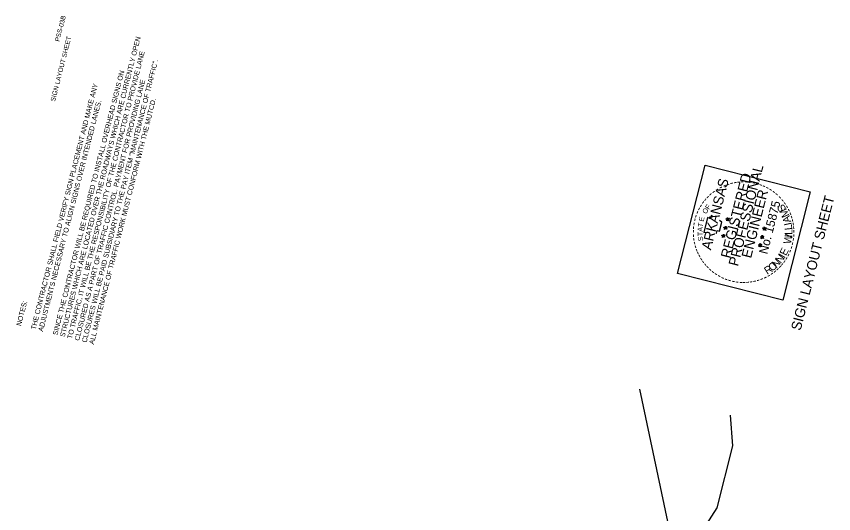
# Model space of a CAD drawing. Extents: x 670003 to 670131, y 737835 to 738003.
# Drawn here: x 670028.6 to 670130.8, y 737940.4 to 738002.6 of the extents above; entities that cross this region are included whole.
import ezdxf

# ---------------------------------------------------------------- set-up
doc = ezdxf.new("R2010")
doc.units = 0
for name, color, linetype in [('R_Alt Surface', 7, 'Continuous'), ('R_Border', 7, 'Continuous'), ('R_Border Notes', 7, 'Continuous'), ('R_Border PE', 7, 'Continuous'), ('R_Border Prem', 7, 'Continuous'), ('R_Exist Surface', 7, 'Continuous'), ('R_SIGN_ANNOT', 7, 'Continuous')]:
    doc.layers.add(name, color=color, linetype=linetype)

msp = doc.modelspace()

# ---------------------------------------------------------------- linework, layer by layer
at = {"layer": 'R_Alt Surface'}
for points in [[(670116.21, 737941.14), (670118.18, 737948.89), (670117.89, 737952.73)], [(670102.43, 737911.4), (670104, 737916.67), (670111.54, 737933.85), (670116.21, 737941.14)]]:
    msp.add_lwpolyline(points, dxfattribs=at)
at = {"layer": 'R_Border PE'}
for p, q in [((670117.32, 737977.26), (670117.48, 737977.27)), ((670117.53, 737977.21), (670117.32, 737977.26)), ((670117.32, 737977.26), (670117.47, 737977.25)), ((670117.32, 737977.26), (670117.46, 737977.24)), ((670117.32, 737977.26), (670117.46, 737977.21)), ((670117.32, 737977.26), (670117.46, 737977.2)), ((670117.32, 737977.26), (670117.45, 737977.19)), ((670117.41, 737977.01), (670117.53, 737977.21)), ((670117.41, 737977.01), (670117.47, 737977.16)), ((670117.41, 737977.01), (670117.48, 737977.15)), ((670117.41, 737977.01), (670117.49, 737977.15)), ((670117.41, 737977.01), (670117.51, 737977.14)), ((670117.41, 737977.01), (670117.52, 737977.14)), ((670117.41, 737977.01), (670117.53, 737977.13)), ((670117.52, 737977.44), (670117.49, 737977.24)), ((670117.52, 737977.44), (670117.51, 737977.25)), ((670117.52, 737977.44), (670117.53, 737977.21)), ((670117.52, 737977.44), (670117.52, 737977.25)), ((670117.52, 737977.44), (670117.54, 737977.29)), ((670117.52, 737977.44), (670117.55, 737977.29)), ((670117.52, 737977.44), (670117.56, 737977.3)), ((670117.75, 737977.29), (670117.53, 737977.21)), ((670117.68, 737977.03), (670117.53, 737977.21)), ((670117.68, 737977.03), (670117.53, 737977.14)), ((670117.75, 737977.29), (670117.55, 737977.25)), ((670117.68, 737977.03), (670117.55, 737977.14)), ((670117.75, 737977.29), (670117.56, 737977.27)), ((670117.68, 737977.03), (670117.56, 737977.15)), ((670117.75, 737977.29), (670117.57, 737977.24)), ((670117.75, 737977.29), (670117.58, 737977.19)), ((670117.68, 737977.03), (670117.58, 737977.19)), ((670117.68, 737977.03), (670117.58, 737977.17)), ((670117.75, 737977.29), (670117.59, 737977.22)), ((670117.75, 737977.29), (670117.6, 737977.19)), ((670117.68, 737977.03), (670117.6, 737977.2)), ((670117.26, 737976.14), (670117.03, 737976.19)), ((670117.03, 737976.19), (670117.2, 737976.19)), ((670117.03, 737976.19), (670117.19, 737976.18)), ((670117.03, 737976.19), (670117.19, 737976.17)), ((670117.03, 737976.19), (670117.18, 737976.14)), ((670117.03, 737976.19), (670117.18, 737976.13)), ((670117.03, 737976.19), (670117.18, 737976.12)), ((670117.14, 737975.94), (670117.26, 737976.14)), ((670117.14, 737975.94), (670117.19, 737976.09)), ((670117.14, 737975.94), (670117.2, 737976.09)), ((670117.14, 737975.94), (670117.21, 737976.08)), ((670117.14, 737975.94), (670117.23, 737976.07)), ((670117.14, 737975.94), (670117.24, 737976.07)), ((670117.14, 737975.94), (670117.26, 737976.06)), ((670117.24, 737976.36), (670117.21, 737976.17)), ((670117.24, 737976.36), (670117.23, 737976.18)), ((670117.24, 737976.36), (670117.26, 737976.14)), ((670117.24, 737976.36), (670117.24, 737976.18)), ((670117.24, 737976.36), (670117.26, 737976.22)), ((670117.24, 737976.36), (670117.27, 737976.23)), ((670117.24, 737976.36), (670117.28, 737976.23)), ((670117.41, 737975.96), (670117.25, 737976.07)), ((670117.47, 737976.22), (670117.26, 737976.14)), ((670117.41, 737975.96), (670117.26, 737976.14)), ((670117.47, 737976.22), (670117.27, 737976.18)), ((670117.47, 737976.22), (670117.27, 737976.2)), ((670117.41, 737975.96), (670117.27, 737976.07)), ((670117.41, 737975.96), (670117.28, 737976.08)), ((670117.47, 737976.22), (670117.3, 737976.12)), ((670117.47, 737976.22), (670117.3, 737976.17)), ((670117.41, 737975.96), (670117.3, 737976.12)), ((670117.41, 737975.96), (670117.3, 737976.1)), ((670117.47, 737976.22), (670117.32, 737976.12)), ((670117.47, 737976.22), (670117.32, 737976.15)), ((670117.41, 737975.96), (670117.32, 737976.12)), ((670122.12, 737976.04), (670121.9, 737976.1)), ((670121.9, 737976.1), (670122.06, 737976.1)), ((670121.9, 737976.1), (670122.06, 737976.09)), ((670121.9, 737976.1), (670122.06, 737976.07)), ((670121.9, 737976.1), (670122.05, 737976.05)), ((670121.9, 737976.1), (670122.05, 737976.04)), ((670121.9, 737976.1), (670122.04, 737976.02)), ((670122, 737975.85), (670122.12, 737976.04)), ((670122, 737975.85), (670122.06, 737975.99)), ((670122, 737975.85), (670122.07, 737975.99)), ((670122, 737975.85), (670122.08, 737975.98)), ((670122, 737975.85), (670122.1, 737975.98)), ((670122, 737975.85), (670122.11, 737975.97)), ((670122, 737975.85), (670122.13, 737975.96)), ((670122.11, 737976.27), (670122.07, 737976.08)), ((670122.11, 737976.27), (670122.09, 737976.09)), ((670122.11, 737976.27), (670122.1, 737976.09)), ((670122.11, 737976.27), (670122.12, 737976.04)), ((670122.11, 737976.27), (670122.13, 737976.12)), ((670122.11, 737976.27), (670122.14, 737976.13)), ((670122.11, 737976.27), (670122.15, 737976.13)), ((670122.27, 737975.86), (670122.11, 737975.97)), ((670122.33, 737976.12), (670122.12, 737976.04)), ((670122.27, 737975.86), (670122.12, 737976.04)), ((670122.33, 737976.12), (670122.14, 737976.08)), ((670122.33, 737976.12), (670122.14, 737976.1)), ((670122.27, 737975.86), (670122.14, 737975.97)), ((670122.27, 737975.86), (670122.15, 737975.99)), ((670122.33, 737976.12), (670122.17, 737976.02)), ((670122.33, 737976.12), (670122.17, 737976.07)), ((670122.27, 737975.86), (670122.17, 737976.02)), ((670122.27, 737975.86), (670122.17, 737976.01)), ((670122.33, 737976.12), (670122.18, 737976.05)), ((670122.33, 737976.12), (670122.19, 737976.02)), ((670122.27, 737975.86), (670122.19, 737976.03)), ((670117, 737975.12), (670116.77, 737975.18)), ((670116.77, 737975.18), (670116.94, 737975.18)), ((670116.77, 737975.18), (670116.93, 737975.17)), ((670116.77, 737975.18), (670116.93, 737975.16)), ((670116.77, 737975.18), (670116.92, 737975.14)), ((670116.77, 737975.18), (670116.93, 737975.12)), ((670116.77, 737975.18), (670116.92, 737975.11)), ((670116.88, 737974.93), (670117, 737975.12)), ((670116.88, 737974.93), (670116.93, 737975.08)), ((670116.88, 737974.93), (670116.94, 737975.08)), ((670116.88, 737974.93), (670116.95, 737975.07)), ((670116.88, 737974.93), (670116.98, 737975.06)), ((670116.88, 737974.93), (670116.99, 737975.06)), ((670116.88, 737974.93), (670117, 737975.05)), ((670116.99, 737975.35), (670116.95, 737975.16)), ((670116.99, 737975.35), (670116.97, 737975.17)), ((670116.99, 737975.35), (670116.98, 737975.17)), ((670116.99, 737975.35), (670117, 737975.12)), ((670116.99, 737975.35), (670117.01, 737975.21)), ((670116.99, 737975.35), (670117.02, 737975.22)), ((670116.99, 737975.35), (670117.02, 737975.22)), ((670117.21, 737975.21), (670117, 737975.12)), ((670117.15, 737974.95), (670117, 737975.12)), ((670117.15, 737974.95), (670117, 737975.06)), ((670117.21, 737975.21), (670117.01, 737975.18)), ((670117.21, 737975.21), (670117.02, 737975.17)), ((670117.15, 737974.95), (670117.02, 737975.07)), ((670117.15, 737974.95), (670117.02, 737975.06)), ((670117.21, 737975.21), (670117.04, 737975.16)), ((670117.21, 737975.21), (670117.05, 737975.11)), ((670117.15, 737974.95), (670117.05, 737975.11)), ((670117.15, 737974.95), (670117.05, 737975.09)), ((670117.21, 737975.21), (670117.06, 737975.13)), ((670117.21, 737975.21), (670117.07, 737975.11)), ((670117.15, 737974.95), (670117.07, 737975.11)), ((670121.84, 737974.97), (670121.62, 737975.03)), ((670121.62, 737975.03), (670121.78, 737975.03)), ((670121.62, 737975.03), (670121.78, 737975.02)), ((670121.62, 737975.03), (670121.78, 737975)), ((670121.62, 737975.03), (670121.77, 737974.98)), ((670121.62, 737975.03), (670121.77, 737974.97)), ((670121.62, 737975.03), (670121.76, 737974.95)), ((670121.72, 737974.78), (670121.84, 737974.97)), ((670121.72, 737974.78), (670121.78, 737974.92)), ((670121.72, 737974.78), (670121.79, 737974.92)), ((670121.72, 737974.78), (670121.8, 737974.92)), ((670121.72, 737974.78), (670121.82, 737974.91)), ((670121.72, 737974.78), (670121.83, 737974.9)), ((670121.72, 737974.78), (670121.84, 737974.9)), ((670121.83, 737975.2), (670121.79, 737975.01)), ((670121.83, 737975.2), (670121.81, 737975.02)), ((670121.83, 737975.2), (670121.84, 737974.97)), ((670121.83, 737975.2), (670121.83, 737975.01)), ((670121.83, 737975.2), (670121.85, 737975.05)), ((670121.83, 737975.2), (670121.86, 737975.06)), ((670121.83, 737975.2), (670121.87, 737975.07)), ((670122.06, 737975.05), (670121.84, 737974.97)), ((670121.99, 737974.79), (670121.84, 737974.97)), ((670121.99, 737974.79), (670121.84, 737974.91)), ((670122.06, 737975.05), (670121.86, 737975.01)), ((670122.06, 737975.05), (670121.86, 737975.03)), ((670121.99, 737974.79), (670121.86, 737974.91)), ((670121.99, 737974.79), (670121.87, 737974.92)), ((670122.06, 737975.05), (670121.88, 737975.01)), ((670121.99, 737974.79), (670121.89, 737974.96)), ((670121.99, 737974.79), (670121.89, 737974.93)), ((670122.06, 737975.05), (670121.9, 737974.96)), ((670122.06, 737975.05), (670121.9, 737974.98)), ((670122.06, 737975.05), (670121.91, 737974.95)), ((670121.99, 737974.79), (670121.91, 737974.96)), ((670121.59, 737973.96), (670121.37, 737974.02)), ((670121.37, 737974.02), (670121.53, 737974.02)), ((670121.37, 737974.02), (670121.53, 737974.01)), ((670121.37, 737974.02), (670121.52, 737973.99)), ((670121.37, 737974.02), (670121.52, 737973.97)), ((670121.37, 737974.02), (670121.51, 737973.95)), ((670121.37, 737974.02), (670121.5, 737973.94)), ((670121.46, 737973.77), (670121.59, 737973.96)), ((670121.46, 737973.77), (670121.52, 737973.92)), ((670121.46, 737973.77), (670121.53, 737973.91)), ((670121.46, 737973.77), (670121.54, 737973.91)), ((670121.46, 737973.77), (670121.56, 737973.9)), ((670121.46, 737973.77), (670121.57, 737973.89)), ((670121.46, 737973.77), (670121.59, 737973.89)), ((670121.57, 737974.19), (670121.54, 737974)), ((670121.57, 737974.19), (670121.56, 737974.01)), ((670121.57, 737974.19), (670121.59, 737973.96)), ((670121.57, 737974.19), (670121.57, 737974)), ((670121.57, 737974.19), (670121.59, 737974.04)), ((670121.57, 737974.19), (670121.6, 737974.05)), ((670121.57, 737974.19), (670121.62, 737974.06)), ((670121.73, 737973.78), (670121.58, 737973.9)), ((670121.8, 737974.04), (670121.59, 737973.96)), ((670121.73, 737973.78), (670121.59, 737973.96)), ((670121.8, 737974.04), (670121.6, 737974)), ((670121.8, 737974.04), (670121.61, 737974.02)), ((670121.73, 737973.78), (670121.61, 737973.9)), ((670121.73, 737973.78), (670121.62, 737973.91)), ((670121.8, 737974.04), (670121.63, 737974)), ((670121.73, 737973.78), (670121.63, 737973.95)), ((670121.73, 737973.78), (670121.63, 737973.92)), ((670121.8, 737974.04), (670121.64, 737973.95)), ((670121.8, 737974.04), (670121.64, 737973.96)), ((670121.8, 737974.04), (670121.65, 737973.94)), ((670121.73, 737973.78), (670121.65, 737973.94))]:
    msp.add_line(p, q, dxfattribs=at)
for points in [[(670115.63, 737977.54), (670115.48, 737977.67), (670115.39, 737977.25), (670115.01, 737977.44), (670114.54, 737975.56)], [(670116.08, 737975.48), (670116.13, 737975.47), (670116.23, 737975.8), (670116.51, 737975.7), (670116.79, 737976.83), (670116.5, 737977.04)], [(670117.32, 737977.26), (670117.75, 737977.29), (670117.41, 737977.01), (670117.52, 737977.44), (670117.68, 737977.03), (670117.32, 737977.26)], [(670114.54, 737975.56), (670115.08, 737975.59)], [(670117.03, 737976.19), (670117.47, 737976.22), (670117.14, 737975.94), (670117.24, 737976.36), (670117.41, 737975.96), (670117.03, 737976.19)], [(670121.9, 737976.1), (670122.33, 737976.12), (670122, 737975.85), (670122.11, 737976.27), (670122.27, 737975.86), (670121.9, 737976.1)], [(670116.77, 737975.18), (670117.21, 737975.21), (670116.88, 737974.93), (670116.99, 737975.35), (670117.15, 737974.95), (670116.77, 737975.18)], [(670121.62, 737975.03), (670122.06, 737975.05), (670121.72, 737974.78), (670121.83, 737975.2), (670121.99, 737974.79), (670121.62, 737975.03)], [(670121.37, 737974.02), (670121.8, 737974.04), (670121.46, 737973.77), (670121.57, 737974.19), (670121.73, 737973.78), (670121.37, 737974.02)]]:
    msp.add_lwpolyline(points, dxfattribs=at)
for centre, radius in [((670117.54, 737977.21), 0.108), ((670117.54, 737977.21), 0.0975), ((670117.54, 737977.21), 0.0904), ((670117.54, 737977.21), 0.083), ((670117.54, 737977.21), 0.0723), ((670117.54, 737977.21), 0.0619), ((670117.54, 737977.21), 0.0672), ((670117.54, 737977.21), 0.0533), ((670117.54, 737977.21), 0.0467), ((670117.54, 737977.21), 0.0388), ((670117.54, 737977.21), 0.031), ((670117.54, 737977.21), 0.0231), ((670117.54, 737977.21), 0.0185), ((670117.54, 737977.21), 0.00901), ((670117.26, 737976.14), 0.108), ((670117.26, 737976.14), 0.0975), ((670117.26, 737976.14), 0.0904), ((670117.26, 737976.14), 0.083), ((670117.26, 737976.14), 0.0723), ((670117.26, 737976.14), 0.0619), ((670117.26, 737976.14), 0.0672), ((670117.26, 737976.14), 0.0533), ((670117.26, 737976.14), 0.0467), ((670117.26, 737976.14), 0.0388), ((670117.26, 737976.14), 0.031), ((670117.26, 737976.14), 0.0231), ((670117.26, 737976.14), 0.0185), ((670117.26, 737976.14), 0.00901), ((670122.12, 737976.04), 0.108), ((670122.12, 737976.04), 0.0975), ((670122.12, 737976.04), 0.0904), ((670122.12, 737976.04), 0.083), ((670122.12, 737976.04), 0.0723), ((670122.12, 737976.04), 0.0672), ((670122.12, 737976.04), 0.0619), ((670122.12, 737976.04), 0.0533), ((670122.12, 737976.04), 0.0467), ((670122.12, 737976.04), 0.0388), ((670122.12, 737976.04), 0.031), ((670122.12, 737976.04), 0.0231), ((670122.12, 737976.04), 0.0185), ((670122.12, 737976.04), 0.00901), ((670117, 737975.13), 0.108), ((670117, 737975.13), 0.0975), ((670117, 737975.13), 0.0904), ((670117, 737975.13), 0.083), ((670117, 737975.13), 0.0723), ((670117, 737975.13), 0.0672), ((670117, 737975.13), 0.0619), ((670117, 737975.13), 0.0533), ((670117, 737975.13), 0.0467), ((670117, 737975.13), 0.0388), ((670117, 737975.13), 0.031), ((670117, 737975.13), 0.0231), ((670117, 737975.13), 0.0185), ((670117, 737975.13), 0.00901), ((670121.84, 737974.97), 0.108), ((670121.84, 737974.97), 0.0975), ((670121.84, 737974.97), 0.0904), ((670121.84, 737974.97), 0.083), ((670121.84, 737974.97), 0.0723), ((670121.84, 737974.97), 0.0672), ((670121.84, 737974.97), 0.0619), ((670121.84, 737974.97), 0.0533), ((670121.84, 737974.97), 0.0467), ((670121.84, 737974.97), 0.0388), ((670121.84, 737974.97), 0.031), ((670121.84, 737974.97), 0.0231), ((670121.84, 737974.97), 0.0185), ((670121.84, 737974.97), 0.00901), ((670121.59, 737973.96), 0.108), ((670121.59, 737973.96), 0.0975), ((670121.59, 737973.96), 0.0904), ((670121.59, 737973.96), 0.083), ((670121.59, 737973.96), 0.0723), ((670121.59, 737973.96), 0.0672), ((670121.59, 737973.96), 0.0619), ((670121.59, 737973.96), 0.0533), ((670121.59, 737973.96), 0.0467), ((670121.59, 737973.96), 0.0388), ((670121.59, 737973.96), 0.031), ((670121.59, 737973.96), 0.0231), ((670121.59, 737973.96), 0.0185), ((670121.59, 737973.96), 0.00901)]:
    msp.add_circle(centre, radius, dxfattribs=at)
at = {"layer": 'R_Border Prem'}
msp.add_lwpolyline([(670111.27, 737970.43), (670114.7, 737983.95), (670127.85, 737980.62), (670124.42, 737967.1)], close=True, dxfattribs=at)
at = {"layer": 'R_Exist Surface'}
msp.add_lwpolyline([(670106.5, 737955.96), (670111.38, 737932.93), (670111.49, 737932.44), (670111.5, 737932.42), (670111.75, 737931.4), (670112, 737930.45), (670111.98, 737930.4), (670111.02, 737926.65), (670110.93, 737926.54), (670109.57, 737925), (670103.15, 737910.71), (670100.52, 737904.76), (670095.74, 737887.59), (670089.99, 737866.93), (670089.12, 737859.5), (670089.03, 737858.69), (670088.89, 737857.11), (670088.05, 737846.44), (670087.72, 737842.3), (670087.68, 737841.87), (670087.51, 737841.51), (670087.26, 737840.96)], dxfattribs=at)

# ---------------------------------------------------------------- texts
at = {"layer": 'R_Border'}
for s, height, p in [('PSS-03B', 0.586, (670034.01, 737999.36)), ('SIGN LAYOUT SHEET', 0.5862, (670033.46, 737991.88))]:
    msp.add_text(s, height=height, rotation=75.7686, dxfattribs=at).set_placement(p)
at = {"layer": 'R_Border Notes'}
msp.add_text('SIGN LAYOUT SHEET', height=1.25, rotation=75.7686, dxfattribs=at).set_placement((670126.64, 737963.22))
at = {"layer": 'R_Border PE'}
for s, height, rotation, p in [('PROFESSIONAL', 1.25, 75.7686, (670118.82, 737971.26)), ('REGISTERED', 1.25, 75.7686, (670117.85, 737972.25)), ('ARKANSAS', 1.25, 75.7686, (670115.44, 737973.29)), ('-', 0.875, 19.4438, (670117.51, 737981.17)), ('-', 1, 15.4369, (670117.92, 737981.27)), ('-', 1, 10.4313, (670118.34, 737981.37)), ('-', 1, 6.3414, (670118.73, 737981.44)), ('-', 1, 0.8918, (670119.12, 737981.49)), ('-', 1, 356.3179, (670119.6, 737981.49)), ('-', 1, 352.3647, (670120.09, 737981.48)), ('-', 1, 350.0987, (670120.54, 737981.4)), ('-', 1, 345.7092, (670120.92, 737981.32)), ('-', 1, 339.2857, (670121.32, 737981.21)), ('-', 1, 36.2983, (670115.83, 737980.18)), ('-', 1, 31.3471, (670116.22, 737980.47)), ('-', 1, 25.6483, (670116.64, 737980.73)), ('-', 1, 22.4207, (670117.09, 737980.96)), ('ENGINEER', 1.25, 75.7686, (670120.45, 737972.26)), ('-', 1, 336.7638, (670121.71, 737981.07)), ('-', 1, 331.5312, (670122.11, 737980.9)), ('-', 1, 328.6366, (670122.51, 737980.68)), ('-', 1, 323.6572, (670122.89, 737980.44)), ('-', 1, 49.8896, (670114.9, 737979.24)), ('-', 1, 45.4094, (670115.16, 737979.55)), ('-', 1, 41.6312, (670115.48, 737979.88)), ('No. 15875', 1.1, 75.7686, (670122.48, 737972.77)), ('-', 1, 320.3883, (670123.23, 737980.18)), ('-', 1, 314.8398, (670123.62, 737979.83)), ('-', 1, 309.6138, (670123.95, 737979.49)), ('-', 1, 62.9734, (670114.2, 737978.13)), ('-', 1, 58.1047, (670114.4, 737978.49)), ('-', 1, 53.6236, (670114.64, 737978.9)), ('O', 0.625, 66.2201, (670114.9, 737977.82)), ('F', 0.625, 55.8392, (670115.18, 737978.36)), ('S', 0.962, 121.462, (670124.91, 737978.46)), ('M', 0.962, 113.3256, (670125.26, 737977.67)), ('-', 1, 307.0223, (670124.23, 737979.14)), ('-', 1, 301.5339, (670124.5, 737978.76)), ('-', 1, 296.8536, (670124.73, 737978.37)), ('-', 1, 73.5116, (670113.87, 737977.27)), ('-', 1, 67.9303, (670114.02, 737977.71)), ('E', 0.625, 76.6009, (670114.52, 737976.87)), ('A', 0.962, 105.7601, (670125.48, 737976.9)), ('-', 1, 291.5049, (670124.93, 737977.96)), ('-', 1, 288.0176, (670125.08, 737977.57)), ('-', 1, 81.6654, (670113.68, 737976.35)), ('-', 1, 75.9548, (670113.76, 737976.83)), ('T', 0.625, 81.7913, (670114.42, 737976.19)), ('I', 0.962, 102.3343, (670125.55, 737976.54)), ('L', 0.962, 96.339, (670125.62, 737975.9)), ('-', 1, 283.1254, (670125.21, 737977.19)), ('-', 1, 280.0202, (670125.31, 737976.76)), ('-', 1, 89.3987, (670113.63, 737975.46)), ('-', 1, 85.9879, (670113.63, 737975.89)), ('T', 0.625, 92.1721, (670114.42, 737975.11)), ('A', 0.625, 86.9817, (670114.39, 737975.65)), ('W', 0.962, 78.7816, (670125.43, 737974.05)), ('L', 0.962, 90.3438, (670125.62, 737975.27)), ('-', 1, 276.487, (670125.37, 737976.34)), ('-', 1, 271.2428, (670125.42, 737975.9)), ('-', 1, 94.9446, (670113.66, 737974.97)), ('-', 1, 100.0758, (670113.72, 737974.54)), ('-', 1, 104.5604, (670113.82, 737974.11)), ('S', 0.625, 97.3626, (670114.48, 737974.51)), ('I', 0.962, 86.9179, (670125.59, 737974.9)), ('-', 1, 261.5852, (670125.39, 737974.96)), ('-', 1, 267.0543, (670125.43, 737975.42)), ('-', 1, 109.8321, (670113.95, 737973.69)), ('-', 1, 112.0003, (670114.1, 737973.28)), ('E', 0.962, 63.7221, (670124.83, 737972.57)), ('-', 1, 248.884, (670125.06, 737973.56)), ('-', 1, 252.2868, (670125.21, 737974)), ('-', 1, 257.3603, (670125.31, 737974.45)), ('-', 1, 114.7192, (670114.26, 737972.94)), ('-', 1, 118.7308, (670114.45, 737972.61)), ('-', 1, 124.1916, (670114.67, 737972.26)), ('N', 0.962, 52.7308, (670124.16, 737971.62)), ('I', 0.962, 60.2962, (670124.64, 737972.26)), ('-', 1, 238.5668, (670124.67, 737972.7)), ('-', 1, 243.3241, (670124.88, 737973.11)), ('-', 1, 126.3827, (670114.9, 737971.94)), ('-', 1, 130.001, (670115.18, 737971.61)), ('-', 1, 133.8392, (670115.45, 737971.33)), ('R', 0.962, 32.1757, (670122.47, 737970.25)), ('O', 0.962, 38.8847, (670123.07, 737970.63)), ('N', 0.962, 45.1654, (670123.59, 737971.05)), ('-', 1, 227.3389, (670123.96, 737971.7)), ('-', 1, 230.3687, (670124.18, 737971.97)), ('-', 1, 234.3298, (670124.44, 737972.32)), ('-', 1, 138.6399, (670115.77, 737971.04)), ('-', 1, 143.5428, (670116.1, 737970.79)), ('-', 1, 148.163, (670116.45, 737970.56)), ('-', 1, 214.7024, (670123.02, 737970.84)), ('-', 1, 220.4149, (670123.36, 737971.11)), ('-', 1, 223.8583, (670123.67, 737971.39)), ('-', 1, 151.2295, (670116.86, 737970.34)), ('-', 1, 156.9698, (670117.26, 737970.14)), ('-', 1, 160.9549, (670117.67, 737969.99)), ('-', 1, 164.8308, (670118.09, 737969.87)), ('-', 1, 169.9644, (670118.54, 737969.78)), ('-', 1, 174.7165, (670118.95, 737969.72)), ('-', 1, 177.4835, (670119.42, 737969.69)), ('-', 1, 181.2264, (670119.8, 737969.7)), ('-', 1, 184.856, (670120.22, 737969.73)), ('-', 1, 189.8329, (670120.62, 737969.8)), ('-', 1, 191.4974, (670121.04, 737969.88)), ('-', 1, 196.2157, (670121.45, 737970.01)), ('-', 1, 201.662, (670121.85, 737970.17)), ('-', 1, 206.4867, (670122.26, 737970.36)), ('-', 1, 209.9924, (670122.67, 737970.59))]:
    msp.add_text(s, height=height, rotation=rotation, dxfattribs=at).set_placement(p)
at = {"layer": 'R_SIGN_ANNOT'}
for s, p in [('STRUCTURES WHICH ARE LOCATED OVER THE ROADWAYS WHICH ARE CURRENTLY OPEN ', (670034.67, 737962.44)), ('TO TRAFFIC, IT WILL BE THE RESPONSIBILITY OF THE CONTRACTOR TO PROVIDE LANE ', (670035.58, 737962.21)), ('CLOSURES WILL BE PAID SUBSIDIARY TO THE PAY ITEM "MAINTENANCE OF TRAFFIC". ', (670037.4, 737961.75)), ('SINCE THE CONTRACTOR WILL BE REQUIRED TO INSTALL OVERHEAD SIGNS ON ', (670033.77, 737962.67)), ('THE CONTRACTOR SHALL FIELD VERIFY SIGN PLACEMENT AND MAKE ANY ', (670031.04, 737963.36)), ('CLOSURED AS A PART OF TRAFFIC CONTROL. PAYMENT FOR PROVIDING LANE ', (670036.49, 737961.98)), ('ADJUSTMENTS NECESSARY TO ALIGN SIGNS OVER INTENDED LANES.', (670031.95, 737963.13)), ('ALL MAINTENANCE OF TRAFFIC WORK MUST CONFORM WITH THE MUTCD.', (670038.31, 737961.52)), ('NOTES: ', (670029.22, 737963.82))]:
    msp.add_text(s, height=0.625, rotation=75.7686, dxfattribs=at).set_placement(p)

doc.saveas('drawing.dxf')
